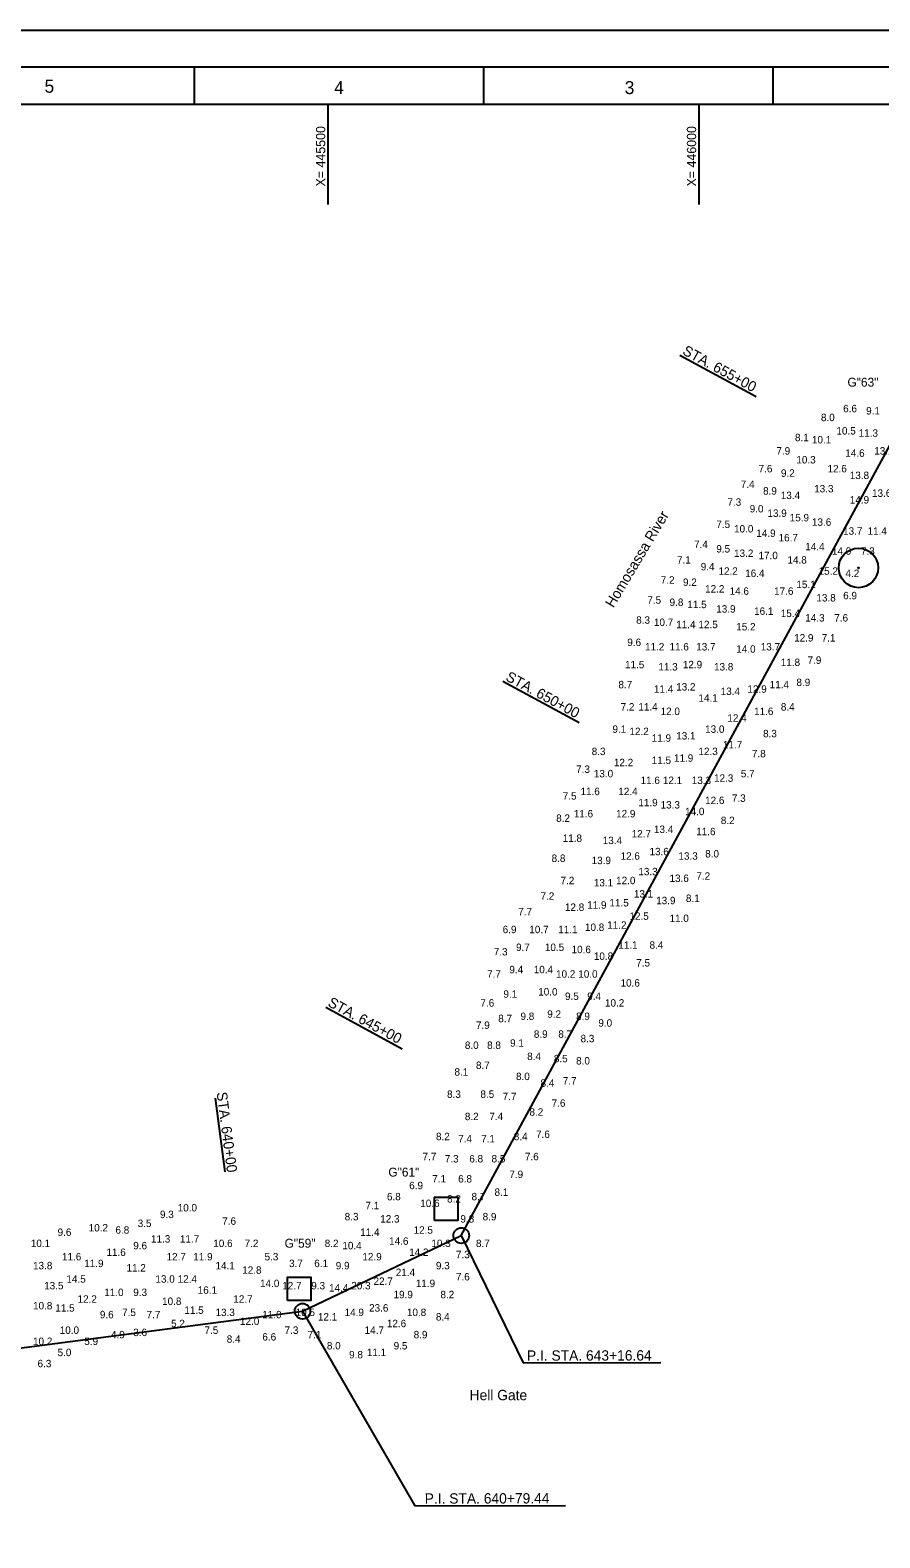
# Model space of a CAD drawing. Extents: x 442804 to 447204, y 1614037 to 1617437.
# Drawn here: x 445098 to 446244, y 1615405 to 1617437 of the extents above; entities that cross this region are included whole.
import ezdxf

# ---------------------------------------------------------------- set-up
doc = ezdxf.new("R2010")
doc.units = 0
for name, color, linetype in [('Default', 7, 'Continuous'), ('G-ANNO-NPLT', 7, 'Continuous'), ('G-ANNO-TTLB', 7, 'Continuous'), ('V-ALGN-TEXT', 7, 'Continuous'), ('V-ANNO-SYMB', 7, 'Continuous'), ('V-CHAN-CNTR', 7, 'Continuous'), ('V-CHAN-CNTR-IDEN', 7, 'Continuous'), ('V-CHAN-NAID', 7, 'Continuous'), ('V-SITE-WATR', 7, 'Continuous'), ('V-TOPO-COOR-STAT', 7, 'Continuous')]:
    doc.layers.add(name, color=color, linetype=linetype)

msp = doc.modelspace()

# ---------------------------------------------------------------- linework, layer by layer
at = {"layer": 'G-ANNO-NPLT'}
msp.add_lwpolyline([(442804.3, 1617437.2), (447204.3, 1617437.2), (447204.3, 1614037.3), (442804.3, 1614037.3)], close=True, dxfattribs=at)
at = {"layer": 'G-ANNO-TTLB'}
for p, q in [((445319.3, 1617387.2), (445319.3, 1617337.2)), ((445709.3, 1617387.2), (445709.3, 1617337.2)), ((446099.3, 1617387.2), (446099.3, 1617337.2))]:
    msp.add_line(p, q, dxfattribs=at)
for points in [[(442854.3, 1614087.3), (447154.3, 1614087.3), (447154.3, 1617387.2), (442854.3, 1617387.2)], [(447104.3, 1617337.2), (442979.3, 1617337.2), (442979.3, 1614137.3), (447104.3, 1614137.3)]]:
    msp.add_lwpolyline(points, close=True, dxfattribs=at)
at = {"layer": 'V-ALGN-TEXT'}
for p, q in [((445974, 1616999.3), (446076.8, 1616943.5)), ((445735.5, 1616559.8), (445838.3, 1616504)), ((445497, 1616120.4), (445599.9, 1616064.6)), ((445347.8, 1615998), (445360.7, 1615898.8)), ((445679.4, 1615812.8), (445762.9, 1615641.2)), ((445465.4, 1615710.8), (445616.6, 1615448.7)), ((445762.9, 1615641.2), (445948.2, 1615641.5)), ((445616.6, 1615448.7), (445819.9, 1615449.1))]:
    msp.add_line(p, q, dxfattribs=at)
at = {"layer": 'V-ANNO-SYMB'}
for centre, radius in [((446214.8, 1616712.5), 26.6), ((446215, 1616712.5), 0.675)]:
    msp.add_circle(centre, radius, dxfattribs=at)
at = {"layer": 'V-CHAN-CNTR'}
for p, q in [((445679.4, 1615812.8), (446277.4, 1616914.8)), ((445465.4, 1615710.8), (445679.4, 1615812.8)), ((444620.4, 1615600.8), (445465.4, 1615710.8))]:
    msp.add_line(p, q, dxfattribs=at)
at = {"layer": 'V-CHAN-CNTR-IDEN'}
for centre in [(445679.4, 1615812.8), (445465.4, 1615710.8)]:
    msp.add_circle(centre, 10.5, dxfattribs=at)
at = {"layer": 'V-CHAN-NAID'}
for points in [[(445643.5, 1615833.3), (445643.5, 1615864.6), (445674.8, 1615864.6), (445674.8, 1615833.3)], [(445445.3, 1615725.2), (445445.3, 1615756.5), (445476.7, 1615756.5), (445476.7, 1615725.2)]]:
    msp.add_lwpolyline(points, close=True, dxfattribs=at)
at = {"layer": 'V-TOPO-COOR-STAT'}
for p, q in [((445500, 1617202.2), (445500, 1617337.2)), ((446000, 1617202.2), (446000, 1617337.2))]:
    msp.add_line(p, q, dxfattribs=at)

# ---------------------------------------------------------------- texts
at = {"layer": 'Default'}
for s, p in [('8.0', (446164.2, 1616910.3)), ('6.6', (446194.2, 1616922.3)), ('9.1', (446225.2, 1616919.3)), ('8.1', (446129.2, 1616883.3)), ('10.5 ', (446185.1, 1616892.3)), ('11.3 ', (446215.1, 1616889.3)), ('7.9', (446104.2, 1616865.3)), ('10.1 ', (446152.1, 1616880.3)), ('13.1 ', (446236.1, 1616865.3)), ('10.3 ', (446131.1, 1616853.3)), ('14.6 ', (446197.1, 1616862.3)), ('7.6', (446080.2, 1616841.3)), ('9.2', (446110.3, 1616835.3)), ('12.6 ', (446173.1, 1616841.3)), ('13.8 ', (446203.1, 1616832.3)), ('7.4', (446056.2, 1616820.3)), ('8.9', (446086.2, 1616811.3)), ('13.4 ', (446110.1, 1616805.3)), ('13.3 ', (446155.1, 1616814.3)), ('13.6 ', (446233.1, 1616808.3)), ('7.3', (446038.2, 1616796.3)), ('9.0', (446068.2, 1616787.3)), ('14.9 ', (446203.1, 1616799.3)), ('7.5', (446023.2, 1616766.3)), ('13.9 ', (446092.1, 1616781.3)), ('15.9 ', (446122.1, 1616775.3)), ('13.6 ', (446152.1, 1616769.3)), ('10.0 ', (446047.1, 1616760.3)), ('14.9 ', (446077.1, 1616754.3)), ('16.7 ', (446107.1, 1616748.3)), ('13.7 ', (446194.1, 1616757.3)), ('11.4 ', (446227.1, 1616757.3)), ('7.4', (445993.2, 1616739.3)), ('9.5', (446023.2, 1616733.3)), ('13.2 ', (446047.1, 1616727.3)), ('17.0 ', (446080.1, 1616724.3)), ('14.4 ', (446143.1, 1616736.3)), ('14.0 ', (446179.1, 1616730.3)), ('7.3', (446218.2, 1616730.3)), ('7.1', (445970.2, 1616718.3)), ('9.4', (446002.2, 1616709.3)), ('12.2 ', (446026.1, 1616703.3)), ('14.8 ', (446119.1, 1616718.3)), ('15.2 ', (446161.1, 1616703.3)), ('7.2', (445948.3, 1616691.3)), ('9.2', (445978.3, 1616688.3)), ('16.4 ', (446062.1, 1616700.3)), ('15.1 ', (446131.1, 1616685.3)), ('4.2', (446197.3, 1616700.3)), ('7.5', (445930.2, 1616664.3)), ('9.8', (445960.2, 1616661.3)), ('12.2 ', (446008.1, 1616679.3)), ('14.6 ', (446041.1, 1616676.3)), ('17.6 ', (446101.1, 1616676.3)), ('13.8 ', (446158.1, 1616667.3)), ('6.9', (446194.2, 1616670.3)), ('11.5 ', (445984.1, 1616658.3)), ('13.9 ', (446023.1, 1616652.3)), ('16.1 ', (446074.1, 1616649.3)), ('15.4 ', (446110.1, 1616646.3)), ('14.3 ', (446143.1, 1616640.3)), ('7.6', (446182.2, 1616640.3)), ('8.3', (445915.2, 1616637.3)), ('10.7 ', (445939.1, 1616634.3)), ('11.4 ', (445969.1, 1616631.3)), ('12.5 ', (445999.1, 1616631.3)), ('15.2 ', (446050.1, 1616628.3)), ('9.6', (445903.2, 1616607.3)), ('11.2 ', (445927.1, 1616601.3)), ('11.6 ', (445960.1, 1616601.3)), ('13.7 ', (445996.1, 1616601.3)), ('13.7 ', (446083.1, 1616601.3)), ('12.9 ', (446128.1, 1616613.3)), ('7.1', (446165.2, 1616613.3)), ('14.0 ', (446050.1, 1616598.3)), ('11.8 ', (446110.1, 1616580.3)), ('7.9', (446146.2, 1616583.3)), ('11.5 ', (445900.1, 1616577.3)), ('11.3 ', (445945.1, 1616574.3)), ('12.9 ', (445978.1, 1616577.3)), ('13.8 ', (446020.1, 1616574.3)), ('8.7', (445891.2, 1616550.3)), ('11.4 ', (445939.1, 1616544.3)), ('13.2 ', (445969.1, 1616547.3)), ('13.4 ', (446029.1, 1616541.3)), ('12.9 ', (446065.1, 1616544.3)), ('11.4 ', (446095.1, 1616550.3)), ('8.9', (446131.2, 1616553.3)), ('7.2', (445894.2, 1616520.3)), ('11.4 ', (445918.1, 1616520.3)), ('14.1 ', (445999.1, 1616532.3)), ('8.4', (446110.2, 1616520.3)), ('12.0 ', (445948.1, 1616514.3)), ('12.4 ', (446038.1, 1616505.3)), ('11.6 ', (446074.1, 1616514.3)), ('9.1', (445883.2, 1616490.3)), ('12.2 ', (445906.1, 1616487.3)), ('11.9 ', (445936.1, 1616478.3)), ('13.1 ', (445969.1, 1616481.3)), ('13.0 ', (446008.1, 1616490.3)), ('8.3', (446086.2, 1616484.3)), ('8.3', (445855.2, 1616460.3)), ('12.3 ', (445999.1, 1616460.3)), ('11.7 ', (446032.1, 1616469.3)), ('7.8', (446071.2, 1616457.3)), ('7.3', (445834.2, 1616436.3)), ('12.2 ', (445885.1, 1616445.3)), ('11.5 ', (445936.1, 1616448.3)), ('11.9 ', (445966.1, 1616451.3)), ('13.0 ', (445858.1, 1616430.3)), ('11.6 ', (445921.1, 1616421.3)), ('12.1 ', (445951.1, 1616421.3)), ('13.3 ', (445990.1, 1616421.3)), ('12.3 ', (446020.1, 1616424.3)), ('5.7', (446056.2, 1616430.3)), ('7.5', (445816.2, 1616400.3)), ('11.6 ', (445840.1, 1616406.3)), ('12.4 ', (445891.1, 1616406.3)), ('7.3', (446044.2, 1616397.3)), ('11.6 ', (445831.1, 1616376.3)), ('12.9 ', (445888.1, 1616376.3)), ('11.9 ', (445918.1, 1616391.3)), ('13.3 ', (445948.1, 1616388.3)), ('14.0 ', (445981.1, 1616379.3)), ('12.6 ', (446008.1, 1616394.3)), ('8.2', (445807.3, 1616370.3)), ('13.4 ', (445939.1, 1616355.3)), ('8.2', (446029.3, 1616367.3)), ('11.8 ', (445816.1, 1616343.3)), ('13.4 ', (445870.1, 1616340.3)), ('12.7 ', (445909.1, 1616349.3)), ('11.6 ', (445996.1, 1616352.3)), ('8.8', (445801.2, 1616316.3)), ('12.6 ', (445894.1, 1616319.3)), ('13.6 ', (445933.1, 1616325.3)), ('13.3 ', (445972.1, 1616319.3)), ('8.0', (446008.2, 1616322.3)), ('13.9 ', (445855.1, 1616313.3)), ('13.3 ', (445918.1, 1616298.3)), ('7.2', (445813.2, 1616286.3)), ('13.1 ', (445858.1, 1616283.3)), ('12.0 ', (445888.1, 1616286.3)), ('13.6 ', (445960.1, 1616289.3)), ('7.2', (445996.3, 1616292.3)), ('7.2', (445786.2, 1616265.3)), ('11.5 ', (445879.1, 1616256.3)), ('13.1 ', (445912.1, 1616268.3)), ('13.9 ', (445942.1, 1616259.3)), ('8.1', (445982.2, 1616262.3)), ('7.7', (445756.2, 1616244.3)), ('12.8 ', (445819.1, 1616250.3)), ('11.9 ', (445849.1, 1616253.3)), ('12.5 ', (445906.1, 1616238.3)), ('11.0 ', (445960.1, 1616235.3)), ('6.9', (445735.2, 1616220.3)), ('10.7 ', (445771.1, 1616220.3)), ('11.1 ', (445810.1, 1616220.3)), ('10.8 ', (445846.1, 1616223.3)), ('11.2 ', (445876.1, 1616226.3)), ('9.7', (445753.2, 1616196.3)), ('10.5 ', (445792.1, 1616196.3)), ('10.6 ', (445828.1, 1616193.3)), ('11.1 ', (445891.1, 1616199.3)), ('8.4', (445933.2, 1616199.3)), ('7.3', (445723.2, 1616190.3)), ('10.8 ', (445858.1, 1616184.3)), ('7.5', (445915.2, 1616175.3)), ('7.7', (445714.2, 1616160.3)), ('9.4', (445744.2, 1616166.3)), ('10.4 ', (445777.1, 1616166.3)), ('10.2 ', (445807.1, 1616160.3)), ('10.0 ', (445837.1, 1616160.3)), ('9.1', (445736.2, 1616133.3)), ('10.0 ', (445783.1, 1616136.3)), ('10.6 ', (445894.1, 1616148.3)), ('7.6', (445705.2, 1616121.3)), ('9.5', (445819.2, 1616130.3)), ('9.4', (445849.2, 1616130.3)), ('10.2 ', (445873.1, 1616121.3)), ('7.9', (445699.2, 1616091.3)), ('8.7', (445729.2, 1616100.3)), ('9.8', (445759.2, 1616103.3)), ('9.2', (445795.3, 1616106.3)), ('8.9', (445834.2, 1616103.3)), ('9.0', (445864.2, 1616094.3)), ('8.9', (445777.2, 1616079.3)), ('8.7', (445810.2, 1616079.3)), ('8.3', (445840.2, 1616073.3)), ('8.0', (445684.2, 1616064.3)), ('8.8', (445714.2, 1616064.3)), ('9.1', (445745.2, 1616067.3)), ('8.7', (445699.2, 1616037.3)), ('8.4', (445768.2, 1616049.3)), ('8.5', (445804.2, 1616046.3)), ('8.0', (445834.2, 1616043.3)), ('8.1', (445670.2, 1616028.3)), ('8.0', (445753.2, 1616022.3)), ('8.4', (445786.2, 1616013.3)), ('7.7', (445816.2, 1616016.3)), ('8.3', (445660.2, 1615998.3)), ('8.5', (445705.2, 1615998.3)), ('7.7', (445735.2, 1615995.3)), ('8.2', (445771.3, 1615974.3)), ('7.6', (445801.2, 1615986.3)), ('8.2', (445684.2, 1615968.3)), ('7.4', (445717.2, 1615968.3)), ('8.2', (445645.3, 1615941.3)), ('7.4', (445675.2, 1615938.3)), ('7.1', (445706.2, 1615938.3)), ('8.4', (445750.2, 1615941.3)), ('7.6', (445780.2, 1615944.3)), ('7.7', (445627.2, 1615914.3)), ('7.3', (445657.2, 1615911.3)), ('6.8', (445690.2, 1615911.3)), ('8.5', (445720.2, 1615911.3)), ('7.6', (445765.2, 1615914.3)), ('7.9', (445744.2, 1615890.3)), ('6.9', (445609.2, 1615875.3)), ('7.1', (445640.2, 1615884.3)), ('6.8', (445675.2, 1615884.3)), ('7.1', (445550.2, 1615848.3)), ('6.8', (445579.2, 1615860.3)), ('10.6 ', (445624.1, 1615851.3)), ('8.2', (445660.3, 1615857.3)), ('8.7', (445693.2, 1615860.3)), ('8.1', (445724.2, 1615866.3)), ('9.3', (445273.2, 1615836.3)), ('10.0 ', (445297.1, 1615845.3)), ('7.6', (445357.2, 1615827.3)), ('8.3', (445522.2, 1615833.3)), ('12.3 ', (445570.1, 1615830.3)), ('9.8', (445678.2, 1615830.3)), ('8.9', (445708.2, 1615833.3)), ('9.6', (445135.2, 1615812.3)), ('10.2 ', (445177.1, 1615818.3)), ('6.8', (445213.2, 1615815.3)), ('3.5', (445243.2, 1615824.3)), ('11.4 ', (445543.1, 1615812.3)), ('12.5 ', (445615.1, 1615815.3)), ('10.1 ', (445099.1, 1615797.3)), ('9.6', (445237.2, 1615794.3)), ('11.3 ', (445261.1, 1615803.3)), ('11.7 ', (445300.1, 1615803.3)), ('10.6 ', (445345.1, 1615797.3)), ('7.2', (445387.3, 1615797.3)), ('8.2', (445495.3, 1615797.3)), ('10.4 ', (445519.1, 1615794.3)), ('14.6 ', (445582.1, 1615800.3)), ('10.3 ', (445639.1, 1615797.3)), ('8.7', (445699.2, 1615797.3)), ('13.8 ', (445102.1, 1615767.3)), ('11.6 ', (445141.1, 1615779.3)), ('11.9 ', (445171.1, 1615770.3)), ('11.6 ', (445201.1, 1615785.3)), ('12.7 ', (445282.1, 1615779.3)), ('11.9 ', (445318.1, 1615779.3)), ('14.1 ', (445348.1, 1615767.3)), ('5.3', (445414.2, 1615779.3)), ('3.7', (445447.2, 1615770.3)), ('6.1', (445481.2, 1615770.3)), ('9.9', (445510.2, 1615767.3)), ('12.9 ', (445546.1, 1615779.3)), ('14.2 ', (445609.1, 1615785.3)), ('9.3', (445645.2, 1615767.3)), ('7.3', (445672.2, 1615782.3)), ('14.5 ', (445147.1, 1615749.3)), ('11.2 ', (445228.1, 1615764.3)), ('13.0 ', (445267.1, 1615749.3)), ('12.4 ', (445297.1, 1615749.3)), ('12.8 ', (445384.1, 1615761.3)), ('22.7 ', (445561.1, 1615746.3)), ('21.4 ', (445591.1, 1615758.3)), ('7.6', (445672.2, 1615752.3)), ('13.5 ', (445117.1, 1615740.3)), ('11.0 ', (445198.1, 1615731.3)), ('9.3', (445237.2, 1615731.3)), ('16.1 ', (445324.1, 1615734.3)), ('14.0 ', (445408.1, 1615743.3)), ('12.7 ', (445438.1, 1615740.3)), ('9.3', (445477.2, 1615740.3)), ('14.4 ', (445501.1, 1615737.3)), ('20.3 ', (445531.1, 1615740.3)), ('19.9 ', (445588.1, 1615728.3)), ('11.9 ', (445618.1, 1615743.3)), ('8.2', (445651.3, 1615728.3)), ('10.8 ', (445102.1, 1615713.3)), ('11.5 ', (445132.1, 1615710.3)), ('12.2 ', (445162.1, 1615722.3)), ('10.8 ', (445276.1, 1615719.3)), ('11.5 ', (445306.1, 1615707.3)), ('12.7 ', (445372.1, 1615722.3)), ('23.6 ', (445555.1, 1615710.3)), ('9.6', (445192.2, 1615701.3)), ('7.5', (445222.2, 1615704.3)), ('7.7', (445255.2, 1615701.3)), ('5.2', (445288.2, 1615689.3)), ('13.3 ', (445348.1, 1615704.3)), ('12.0 ', (445381.1, 1615692.3)), ('11.0 ', (445411.1, 1615701.3)), ('10.5 ', (445456.1, 1615704.3)), ('12.1 ', (445486.1, 1615698.3)), ('14.9 ', (445522.1, 1615704.3)), ('12.6 ', (445579.1, 1615689.3)), ('10.8 ', (445606.1, 1615704.3)), ('8.4', (445645.2, 1615698.3)), ('10.2 ', (445102.1, 1615665.3)), ('10.0 ', (445138.1, 1615680.3)), ('5.9', (445171.2, 1615665.3)), ('4.9', (445207.2, 1615674.3)), ('3.6', (445237.2, 1615677.3)), ('7.5', (445333.2, 1615680.3)), ('8.4', (445363.2, 1615668.3)), ('6.6', (445411.2, 1615671.3)), ('7.3', (445441.2, 1615680.3)), ('7.1', (445472.2, 1615674.3)), ('14.7 ', (445549.1, 1615680.3)), ('8.9', (445615.2, 1615674.3)), ('5.0', (445135.2, 1615650.3)), ('8.0', (445498.2, 1615659.3)), ('9.8', (445528.2, 1615647.3)), ('11.1 ', (445552.1, 1615650.3)), ('9.5', (445588.2, 1615659.3)), ('6.3', (445108.2, 1615635.3))]:
    msp.add_text(s, height=10, dxfattribs=at).set_placement(p)
at = {"layer": 'G-ANNO-TTLB'}
for s, p in [('5', (445117.6, 1617352.9)), ('4', (445508, 1617351.1)), ('3', (445899.7, 1617351.1))]:
    msp.add_text(s, height=17.5, dxfattribs=at).set_placement(p)
at = {"layer": 'V-ALGN-TEXT'}
for s, rotation, p in [('STA. 655+00', 331.5137, (445976.5, 1617001.1)), ('STA. 650+00', 331.5137, (445738.1, 1616561.6)), ('STA. 645+00', 331.5137, (445498.3, 1616122.8)), ('STA. 640+00', 277.4167, (445349.6, 1616005.4)), ('P.I. STA. 643+16.64', 0.0976, (445767.9, 1615644.1)), ('P.I. STA. 640+79.44', 0.0976, (445630.1, 1615451.5))]:
    msp.add_text(s, height=13.92, rotation=rotation, dxfattribs=at).set_placement(p)
at = {"layer": 'V-CHAN-NAID'}
for s, p in [('G"63"', (446200, 1616956.8)), ('G"61"', (445581.1, 1615892.3)), ('G"59"', (445441.2, 1615796.4))]:
    msp.add_text(s, height=12, dxfattribs=at).set_placement(p)
at = {"layer": 'V-SITE-WATR'}
msp.add_text('Homosassa River', height=13.92, rotation=59.1553, dxfattribs=at).set_placement((445884.5, 1616657.9))
msp.add_text('Hell Gate', height=13.92, dxfattribs=at).set_placement((445690.6, 1615590.9))
at = {"layer": 'V-TOPO-COOR-STAT'}
for s, p in [('X= 445500', (445496, 1617226.6)), ('X= 446000', (445996, 1617226.6))]:
    msp.add_text(s, height=12.5, rotation=90, dxfattribs=at).set_placement(p)

doc.saveas('drawing.dxf')
